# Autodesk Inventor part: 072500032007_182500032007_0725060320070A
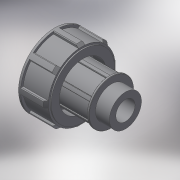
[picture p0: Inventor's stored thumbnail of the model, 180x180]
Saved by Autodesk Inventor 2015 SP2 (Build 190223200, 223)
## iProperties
Created: 2017-04
Part Number: 072500032007_182500032007_0725060320070A
Material: Generic
Description: PLASSON THREADED ADAPTOR 32-3/4"
Document SubType Name: Modeling
Designer: KIM
Density: 1 g/cm^3
Appearance: Default
Author: KIM
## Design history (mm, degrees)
derived "07250.ipt"
feature "Solid1::07250.ipt"
tag "TaggingFeature1"
body "Solid1"
other parameters: "d1" = 26.441, "d2" = 86, "d3" = 18, "d6" = 64, "d7" = 59.52, "d8" = 51.2, "d9" = 32, "d10" = 37.0174, "d12" = 15.8646, "d13" = 21.1528, "d14" = 20.7, "d15" = 48, "d16" = 2.58, "d17" = 34.4, "d18" = 18, "d19" = 21.6, "d24" = 5.2882, "d25" = 2.6441, "d27" = 0, "d28" = 2.11528, "d31" = 0.52882, "d35" = 360 deg, "d41" = 29.337, "d56" = 35.2, "d57" = 3.2, "d58" = 1.6, "d60" = 0, "d61" = 0.26441, "d64" = 0.26441, "d68" = 360 deg, "d_" = 32, "R_" = 26.441, "E_" = 64, "H_" = 86, "l_2" = 18, "d55" = 32
